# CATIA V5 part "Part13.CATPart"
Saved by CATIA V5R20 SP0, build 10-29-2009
Part number: Part13
Bounding box of the stored display mesh (mm): x 0 to 100, y -379.835 to 379.835, z -119.999 to 80
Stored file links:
  E:\新建文件夹 (2)\Part13.CATPart
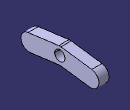
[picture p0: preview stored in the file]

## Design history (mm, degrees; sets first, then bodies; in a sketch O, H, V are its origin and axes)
Body1 (main body)
  Sketch1 on yz-plane, origin (0, 0, 0), H (0, 1, 0), V (0, 0, 1)
    circle A1 centre (0, 0) radius 50
    point P1 (0, 50)
    point P2 (0, 80)
    arc A2 centre (300, -40) radius 80 from (289.4269, -119.2982) to (310.5731, 39.2982) ccw
    arc A3 centre (0, 0) radius 80 from (10.5731, 79.2982) to (-10.5731, 79.2982) ccw
    arc A4 centre (-300, -40) radius 80 from (-310.5731, 39.2982) to (-289.4269, -119.2982) ccw
    line L1 (-310.5731, 39.2982) -> (-10.5731, 79.2982)
    line L2 (10.5731, 79.2982) -> (310.5731, 39.2982)
    line L3 (-15.6278, -82.7917) -> (-289.4269, -119.2982)
    line L4 (15.6278, -82.7917) -> (289.4269, -119.2982)
    arc A5 centre (0, -200) radius 118.2456 from (15.6278, -82.7917) to (-15.6278, -82.7917) ccw
    point P11 (0, -200)
    point P12 (15.6278, -82.7917)
    coincidence: A3 P2, P11 V, A5 P12, P12 L4
    tangency: L1 A4, L2 A2, L3 A4, L4 A2, A5 L4
  Pad1: profile Sketch1, direction (1, 0, 0), length 100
